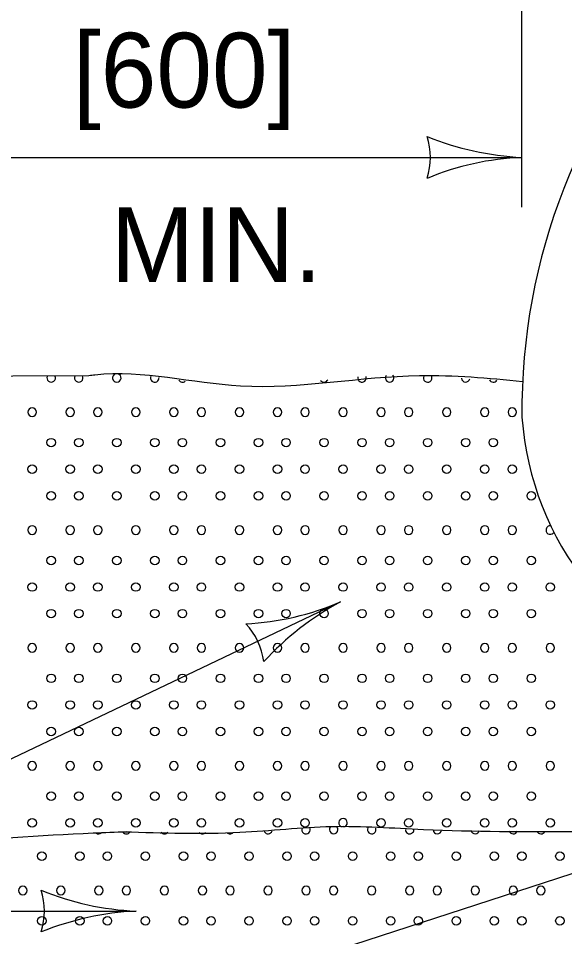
# Model space of a CAD drawing. Extents: x 49991.4 to 50021, y 49987.6 to 50011.4.
# Drawn here: x 50008.339 to 50008.777, y 49993.062 to 49993.799 of the extents above; entities that cross this region are included whole.
import ezdxf

# ---------------------------------------------------------------- set-up
doc = ezdxf.new("R2010")
doc.units = 0
for name, color, linetype in [('Level 1', 7, 'Continuous'), ('Level 2', 7, 'Continuous'), ('Level 3', 7, 'Continuous')]:
    doc.layers.add(name, color=color, linetype=linetype)

msp = doc.modelspace()

# ---------------------------------------------------------------- linework, layer by layer
at = {"layer": 'Level 1'}
msp.add_lwpolyline([(50008.39582, 49993.51254), (50008.33485, 49993.51211), (50008.26098, 49993.50439)], dxfattribs=at)
for centre in [(50008.36559, 49993.45885), (50008.38773, 49993.45885), (50008.41821, 49993.45885), (50008.44869, 49993.45885), (50008.47083, 49993.45885), (50008.50131, 49993.45885), (50008.53179, 49993.45885), (50008.55393, 49993.45885), (50008.58441, 49993.45885), (50008.61489, 49993.45885), (50008.63703, 49993.45885), (50008.66751, 49993.45885), (50008.69799, 49993.45885), (50008.72013, 49993.45885), (50008.35035, 49993.43751), (50008.35035, 49993.43751), (50008.38083, 49993.43751), (50008.40297, 49993.43751), (50008.43345, 49993.43751), (50008.43345, 49993.43751), (50008.46393, 49993.43751), (50008.48607, 49993.43751), (50008.51655, 49993.43751), (50008.51655, 49993.43751), (50008.54703, 49993.43751), (50008.56917, 49993.43751), (50008.59965, 49993.43751), (50008.59965, 49993.43751), (50008.63013, 49993.43751), (50008.65227, 49993.43751), (50008.68275, 49993.43751), (50008.68275, 49993.43751), (50008.71323, 49993.43751), (50008.73537, 49993.43751), (50008.36559, 49993.41617), (50008.38773, 49993.41617), (50008.41821, 49993.41617), (50008.44869, 49993.41617), (50008.47083, 49993.41617), (50008.50131, 49993.41617), (50008.53179, 49993.41617), (50008.55393, 49993.41617), (50008.58441, 49993.41617), (50008.61489, 49993.41617), (50008.63703, 49993.41617), (50008.66751, 49993.41617), (50008.69799, 49993.41617), (50008.72013, 49993.41617), (50008.75061, 49993.41617), (50008.36559, 49993.36425), (50008.38773, 49993.36425), (50008.41821, 49993.36425), (50008.44869, 49993.36425), (50008.47083, 49993.36425), (50008.50131, 49993.36425), (50008.53179, 49993.36425), (50008.55393, 49993.36425), (50008.58441, 49993.36425), (50008.61489, 49993.36425), (50008.63703, 49993.36425), (50008.66751, 49993.36425), (50008.69799, 49993.36425), (50008.72013, 49993.36425), (50008.75061, 49993.36425), (50008.35035, 49993.34291), (50008.35035, 49993.34291), (50008.38083, 49993.34291), (50008.40297, 49993.34291), (50008.43345, 49993.34291), (50008.43345, 49993.34291), (50008.46393, 49993.34291), (50008.48607, 49993.34291), (50008.51655, 49993.34291), (50008.51655, 49993.34291), (50008.54703, 49993.34291), (50008.56917, 49993.34291), (50008.59965, 49993.34291), (50008.59965, 49993.34291), (50008.63013, 49993.34291), (50008.65227, 49993.34291), (50008.68275, 49993.34291), (50008.68275, 49993.34291), (50008.71323, 49993.34291), (50008.73537, 49993.34291), (50008.76585, 49993.34291), (50008.76585, 49993.34291), (50008.36559, 49993.32157), (50008.38773, 49993.32157), (50008.41821, 49993.32157), (50008.44869, 49993.32157), (50008.47083, 49993.32157), (50008.50131, 49993.32157), (50008.53179, 49993.32157), (50008.55393, 49993.32157), (50008.58441, 49993.32157), (50008.61489, 49993.32157), (50008.63703, 49993.32157), (50008.66751, 49993.32157), (50008.69799, 49993.32157), (50008.72013, 49993.32157), (50008.75061, 49993.32157), (50008.36559, 49993.26965), (50008.38773, 49993.26965), (50008.41821, 49993.26965), (50008.44869, 49993.26965), (50008.47083, 49993.26965), (50008.50131, 49993.26965), (50008.53179, 49993.26965), (50008.55393, 49993.26965), (50008.58441, 49993.26965), (50008.61489, 49993.26965), (50008.63703, 49993.26965), (50008.66751, 49993.26965), (50008.69799, 49993.26965), (50008.72013, 49993.26965), (50008.75061, 49993.26965), (50008.35035, 49993.24831), (50008.35035, 49993.24831), (50008.38083, 49993.24831), (50008.40297, 49993.24831), (50008.43345, 49993.24831), (50008.43345, 49993.24831), (50008.46393, 49993.24831), (50008.48607, 49993.24831), (50008.51655, 49993.24831), (50008.51655, 49993.24831), (50008.54703, 49993.24831), (50008.56917, 49993.24831), (50008.59965, 49993.24831), (50008.59965, 49993.24831), (50008.63013, 49993.24831), (50008.65227, 49993.24831), (50008.68275, 49993.24831), (50008.68275, 49993.24831), (50008.71323, 49993.24831), (50008.73537, 49993.24831), (50008.76585, 49993.24831), (50008.76585, 49993.24831), (50008.36559, 49993.22697), (50008.38773, 49993.22697), (50008.41821, 49993.22697), (50008.44869, 49993.22697), (50008.47083, 49993.22697), (50008.50131, 49993.22697), (50008.53179, 49993.22697), (50008.55393, 49993.22697), (50008.58441, 49993.22697), (50008.61489, 49993.22697), (50008.63703, 49993.22697), (50008.66751, 49993.22697), (50008.69799, 49993.22697), (50008.72013, 49993.22697), (50008.75061, 49993.22697), (50008.36559, 49993.17505), (50008.38773, 49993.17505), (50008.41821, 49993.17505), (50008.44869, 49993.17505), (50008.47083, 49993.17505), (50008.50131, 49993.17505), (50008.53179, 49993.17505), (50008.55393, 49993.17505), (50008.58441, 49993.17505), (50008.61489, 49993.17505), (50008.63703, 49993.17505), (50008.66751, 49993.17505), (50008.69799, 49993.17505), (50008.72013, 49993.17505), (50008.75061, 49993.17505), (50008.35035, 49993.15371), (50008.35035, 49993.15371), (50008.38083, 49993.15371), (50008.40297, 49993.15371), (50008.43345, 49993.15371), (50008.43345, 49993.15371), (50008.46393, 49993.15371), (50008.48607, 49993.15371), (50008.51655, 49993.15371), (50008.51655, 49993.15371), (50008.54703, 49993.15371), (50008.56917, 49993.15371), (50008.63013, 49993.15371), (50008.65227, 49993.15371), (50008.68275, 49993.15371), (50008.68275, 49993.15371), (50008.71323, 49993.15371), (50008.73537, 49993.15371), (50008.76585, 49993.15371), (50008.76585, 49993.15371), (50008.35806, 49993.1269), (50008.38854, 49993.1269), (50008.41068, 49993.1269), (50008.44116, 49993.1269), (50008.47164, 49993.1269), (50008.49378, 49993.1269), (50008.52426, 49993.1269), (50008.55474, 49993.1269), (50008.57688, 49993.1269), (50008.60736, 49993.1269), (50008.63784, 49993.1269), (50008.65998, 49993.1269), (50008.69046, 49993.1269), (50008.72094, 49993.1269), (50008.74308, 49993.1269), (50008.77356, 49993.1269), (50008.35806, 49993.07497), (50008.38854, 49993.07497), (50008.41068, 49993.07497), (50008.44116, 49993.07497), (50008.47164, 49993.07497), (50008.49378, 49993.07497), (50008.52426, 49993.07497), (50008.55474, 49993.07497), (50008.57688, 49993.07497), (50008.60736, 49993.07497), (50008.63784, 49993.07497), (50008.65998, 49993.07497), (50008.69046, 49993.07497), (50008.72094, 49993.07497), (50008.74308, 49993.07497), (50008.77356, 49993.07497)]:
    msp.add_circle(centre, 0.00341, dxfattribs=at)
for centre, start, end in [((50008.36559, 49993.51077), 153.23537, 27.57353), ((50008.38773, 49993.51077), 150.24031, 30.56859), ((50008.41821, 49993.51077), 107.30225, 74.08109), ((50008.44869, 49993.51077), 157.88883, 7.63875), ((50008.61489, 49993.51077), 167.00998, 21.46218), ((50008.63703, 49993.51077), 143.12021, 39.07302), ((50008.66751, 49993.51077), 153.48041, 19.95698), ((50008.47083, 49993.51077), 213.15682, 310.21478), ((50008.58441, 49993.51077), 216.07651, 335.33116), ((50008.69799, 49993.51077), 183.46069, 349.97671), ((50008.72013, 49993.51077), 206.01138, 327.42602), ((50008.35035, 49993.48334), 0, 180), ((50008.35035, 49993.48323), 180, 0), ((50008.35035, 49993.48323), 180, 0), ((50008.38083, 49993.48334), 0, 180), ((50008.38083, 49993.48323), 180, 0), ((50008.40297, 49993.48334), 0, 180), ((50008.40297, 49993.48323), 180, 0), ((50008.43345, 49993.48334), 0, 180), ((50008.43345, 49993.48323), 180, 0), ((50008.43345, 49993.48323), 180, 0), ((50008.46393, 49993.48334), 0, 180), ((50008.46393, 49993.48323), 180, 0), ((50008.48607, 49993.48334), 0, 180), ((50008.48607, 49993.48323), 180, 0), ((50008.51655, 49993.48334), 0, 180), ((50008.51655, 49993.48323), 180, 0), ((50008.51655, 49993.48323), 180, 0), ((50008.54703, 49993.48334), 0, 180), ((50008.54703, 49993.48323), 180, 0), ((50008.56917, 49993.48334), 0, 180), ((50008.56917, 49993.48323), 180, 0), ((50008.59965, 49993.48334), 0, 180), ((50008.59965, 49993.48323), 180, 0), ((50008.59965, 49993.48323), 180, 0), ((50008.63013, 49993.48334), 0, 180), ((50008.63013, 49993.48323), 180, 0), ((50008.65227, 49993.48334), 0, 180), ((50008.65227, 49993.48323), 180, 0), ((50008.68275, 49993.48334), 0, 180), ((50008.68275, 49993.48323), 180, 0), ((50008.68275, 49993.48323), 180, 0), ((50008.71323, 49993.48334), 0, 180), ((50008.71323, 49993.48323), 180, 0), ((50008.73537, 49993.48334), 0, 180), ((50008.73537, 49993.48323), 180, 0), ((50008.35035, 49993.38874), 0, 180), ((50008.35035, 49993.38863), 180, 0), ((50008.35035, 49993.38863), 180, 0), ((50008.38083, 49993.38874), 0, 180), ((50008.38083, 49993.38863), 180, 0), ((50008.40297, 49993.38874), 0, 180), ((50008.40297, 49993.38863), 180, 0), ((50008.43345, 49993.38874), 0, 180), ((50008.43345, 49993.38863), 180, 0), ((50008.43345, 49993.38863), 180, 0), ((50008.46393, 49993.38874), 0, 180), ((50008.46393, 49993.38863), 180, 0), ((50008.48607, 49993.38874), 0, 180), ((50008.48607, 49993.38863), 180, 0), ((50008.51655, 49993.38874), 0, 180), ((50008.51655, 49993.38863), 180, 0), ((50008.51655, 49993.38863), 180, 0), ((50008.54703, 49993.38874), 0, 180), ((50008.54703, 49993.38863), 180, 0), ((50008.56917, 49993.38874), 0, 180), ((50008.56917, 49993.38863), 180, 0), ((50008.59965, 49993.38874), 0, 180), ((50008.59965, 49993.38863), 180, 0), ((50008.59965, 49993.38863), 180, 0), ((50008.63013, 49993.38874), 0, 180), ((50008.63013, 49993.38863), 180, 0), ((50008.65227, 49993.38874), 0, 180), ((50008.65227, 49993.38863), 180, 0), ((50008.68275, 49993.38874), 0, 180), ((50008.68275, 49993.38863), 180, 0), ((50008.68275, 49993.38863), 180, 0), ((50008.71323, 49993.38874), 0, 180), ((50008.71323, 49993.38863), 180, 0), ((50008.73537, 49993.38874), 0, 180), ((50008.73537, 49993.38863), 180, 0), ((50008.76585, 49993.38874), 81.22167, 180), ((50008.76585, 49993.38863), 180, 332.77727), ((50008.76585, 49993.38863), 180, 332.77727), ((50008.35035, 49993.29414), 0, 180), ((50008.38083, 49993.29414), 0, 180), ((50008.40297, 49993.29414), 0, 180), ((50008.43345, 49993.29414), 0, 180), ((50008.46393, 49993.29414), 0, 180), ((50008.48607, 49993.29414), 0, 180), ((50008.51655, 49993.29414), 0, 180), ((50008.54703, 49993.29414), 0, 180), ((50008.56917, 49993.29414), 0, 180), ((50008.59965, 49993.29414), 0, 180), ((50008.63013, 49993.29414), 0, 180), ((50008.65227, 49993.29414), 0, 180), ((50008.68275, 49993.29414), 0, 180), ((50008.71323, 49993.29414), 0, 180), ((50008.73537, 49993.29414), 0, 180), ((50008.76585, 49993.29414), 0, 180), ((50008.35035, 49993.29403), 180, 0), ((50008.35035, 49993.29403), 180, 0), ((50008.38083, 49993.29403), 180, 0), ((50008.40297, 49993.29403), 180, 0), ((50008.43345, 49993.29403), 180, 0), ((50008.43345, 49993.29403), 180, 0), ((50008.46393, 49993.29403), 180, 0), ((50008.48607, 49993.29403), 180, 0), ((50008.51655, 49993.29403), 180, 0), ((50008.51655, 49993.29403), 180, 0), ((50008.54703, 49993.29403), 180, 0), ((50008.56917, 49993.29403), 180, 0), ((50008.59965, 49993.29403), 180, 0), ((50008.59965, 49993.29403), 180, 0), ((50008.63013, 49993.29403), 180, 0), ((50008.65227, 49993.29403), 180, 0), ((50008.68275, 49993.29403), 180, 0), ((50008.68275, 49993.29403), 180, 0), ((50008.71323, 49993.29403), 180, 0), ((50008.73537, 49993.29403), 180, 0), ((50008.76585, 49993.29403), 180, 0), ((50008.76585, 49993.29403), 180, 0), ((50008.35035, 49993.19954), 0, 180), ((50008.38083, 49993.19954), 0, 180), ((50008.40297, 49993.19954), 0, 180), ((50008.43345, 49993.19954), 0, 180), ((50008.46393, 49993.19954), 0, 180), ((50008.48607, 49993.19954), 0, 180), ((50008.51655, 49993.19954), 0, 180), ((50008.54703, 49993.19954), 0, 180), ((50008.56917, 49993.19954), 0, 180), ((50008.59965, 49993.19954), 0, 180), ((50008.63013, 49993.19954), 0, 180), ((50008.65227, 49993.19954), 0, 180), ((50008.68275, 49993.19954), 0, 180), ((50008.71323, 49993.19954), 0, 180), ((50008.73537, 49993.19954), 0, 180), ((50008.76585, 49993.19954), 0, 180), ((50008.35035, 49993.19943), 180, 0), ((50008.35035, 49993.19943), 180, 0), ((50008.38083, 49993.19943), 180, 0), ((50008.40297, 49993.19943), 180, 0), ((50008.43345, 49993.19943), 180, 0), ((50008.43345, 49993.19943), 180, 0), ((50008.46393, 49993.19943), 180, 0), ((50008.48607, 49993.19943), 180, 0), ((50008.51655, 49993.19943), 180, 0), ((50008.51655, 49993.19943), 180, 0), ((50008.54703, 49993.19943), 180, 0), ((50008.56917, 49993.19943), 180, 0), ((50008.59965, 49993.19943), 180, 0), ((50008.59965, 49993.19943), 180, 0), ((50008.63013, 49993.19943), 180, 0), ((50008.65227, 49993.19943), 180, 0), ((50008.68275, 49993.19943), 180, 0), ((50008.68275, 49993.19943), 180, 0), ((50008.71323, 49993.19943), 180, 0), ((50008.73537, 49993.19943), 180, 0), ((50008.76585, 49993.19943), 180, 0), ((50008.76585, 49993.19943), 180, 0), ((50008.56998, 49993.14823), 158.83492, 29.86308), ((50008.59212, 49993.14823), 138.09674, 40.51125), ((50008.59965, 49993.15371), 277.54356, 259.36197), ((50008.59965, 49993.15371), 277.54356, 259.36197), ((50008.40378, 49993.14823), 236.10955, 308.5912), ((50008.42592, 49993.14823), 215.23737, 325.05539), ((50008.4564, 49993.14823), 217.53937, 321.7747), ((50008.4564, 49993.14823), 217.53937, 321.7747), ((50008.48688, 49993.14823), 221.66986, 317.63215), ((50008.50902, 49993.14823), 224.54309, 314.91029), ((50008.5395, 49993.14823), 208.315, 341.40784), ((50008.5395, 49993.14823), 208.315, 341.40784), ((50008.6226, 49993.14823), 155.4624, 19.69807), ((50008.6226, 49993.14823), 155.4624, 19.69807), ((50008.65308, 49993.14823), 176.54065, 359.93573), ((50008.67522, 49993.14823), 184.06264, 354.33769), ((50008.7057, 49993.14823), 191.30047, 347.09981), ((50008.7057, 49993.14823), 191.30047, 347.09981), ((50008.73618, 49993.14823), 198.74083, 339.65981), ((50008.75832, 49993.14823), 204.35984, 334.04122), ((50008.34282, 49993.09946), 0, 180), ((50008.34282, 49993.09935), 180, 0), ((50008.3733, 49993.09946), 0, 180), ((50008.3733, 49993.09935), 180, 0), ((50008.3733, 49993.09935), 180, 0), ((50008.40378, 49993.09946), 0, 180), ((50008.40378, 49993.09935), 180, 0), ((50008.42592, 49993.09946), 0, 180), ((50008.42592, 49993.09935), 180, 0), ((50008.4564, 49993.09946), 0, 180), ((50008.4564, 49993.09935), 180, 0), ((50008.4564, 49993.09935), 180, 0), ((50008.48688, 49993.09946), 0, 180), ((50008.48688, 49993.09935), 180, 0), ((50008.50902, 49993.09946), 0, 180), ((50008.50902, 49993.09935), 180, 0), ((50008.5395, 49993.09946), 0, 180), ((50008.5395, 49993.09935), 180, 0), ((50008.5395, 49993.09935), 180, 0), ((50008.56998, 49993.09946), 0, 180), ((50008.56998, 49993.09935), 180, 0), ((50008.59212, 49993.09946), 0, 180), ((50008.59212, 49993.09935), 180, 0), ((50008.6226, 49993.09946), 0, 180), ((50008.6226, 49993.09935), 180, 0), ((50008.6226, 49993.09935), 180, 0), ((50008.65308, 49993.09946), 0, 180), ((50008.65308, 49993.09935), 180, 0), ((50008.67522, 49993.09946), 0, 180), ((50008.67522, 49993.09935), 180, 0), ((50008.7057, 49993.09946), 0, 180), ((50008.7057, 49993.09935), 180, 0), ((50008.7057, 49993.09935), 180, 0), ((50008.73618, 49993.09946), 0, 180), ((50008.73618, 49993.09935), 180, 0), ((50008.75832, 49993.09946), 0, 180), ((50008.75832, 49993.09935), 180, 0)]:
    msp.add_arc(centre, 0.00341, start, end, dxfattribs=at)
for centre, major_axis, ratio, start_param, end_param in [((50009.25853, 49993.48472), (-0.51524, -0.01494), 0.976362, 4.796646, 6.264407), ((50008.96776, 49993.49725), (0, -0.23546), 0.956933, 4.789023, 6.027407)]:
    msp.add_ellipse(centre, major_axis=major_axis, ratio=ratio, start_param=start_param, end_param=end_param, dxfattribs=at)
for points in [[(50008.74365, 49993.50775), (50008.66106, 49993.51249), (50008.51744, 49993.50422), (50008.4006, 49993.5131), (50008.39582, 49993.51254)], [(50008.78607, 49993.1464), (50008.66427, 49993.1481), (50008.59057, 49993.1505), (50008.51697, 49993.1458), (50008.42407, 49993.1463)], [(50008.42607, 49993.1464), (50008.39927, 49993.1453), (50008.27067, 49993.13723), (50008.25476, 49993.13615)]]:
    msp.add_spline(points, degree=3, dxfattribs=at)
at = {"layer": 'Level 3'}
for p, q in [((50008.7431, 49993.64779), (50008.7431, 49994.72745)), ((50008.2631, 49993.68779), (50008.7431, 49993.68779)), ((50008.59757, 49993.33099), (50008.07804, 49993.08287)), ((50008.07804, 49992.88403), (50009.08365, 49993.21045)), ((50008.07804, 49993.08287), (50008.43365, 49993.08287))]:
    msp.add_line(p, q, dxfattribs=at)
for centre, radius, start, end in [((50008.61488, 49993.68779), 0.05477, 342.13882, 17.86118), ((50008.75459, 49993.9205), 0.233, 247.92284, 267.17269), ((50008.75226, 49993.46565), 0.22232, 92.36048, 112.54399), ((50008.51011, 49993.53539), 0.22232, 272.9843, 293.16781), ((50008.70823, 49993.12595), 0.233, 118.3556, 137.60545), ((50008.48188, 49993.27574), 0.05477, 7.66711, 43.38947), ((50008.4428, 49993.305), 0.22232, 247.45601, 267.63952), ((50008.30543, 49993.08287), 0.05477, 342.13882, 17.86118), ((50008.44514, 49992.85016), 0.233, 92.82731, 112.07716)]:
    msp.add_arc(centre, radius, start, end, dxfattribs=at)

# ---------------------------------------------------------------- texts
at = {"layer": 'Level 2'}
for s, p in [('[600]', (50008.383, 49993.72779)), ('MIN.', (50008.41335, 49993.58779))]:
    msp.add_text(s, height=0.06, dxfattribs=at).set_placement(p)

doc.saveas('drawing.dxf')
